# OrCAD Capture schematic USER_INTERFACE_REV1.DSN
size A; title: User Interface Schematic; rev: <Rev1>
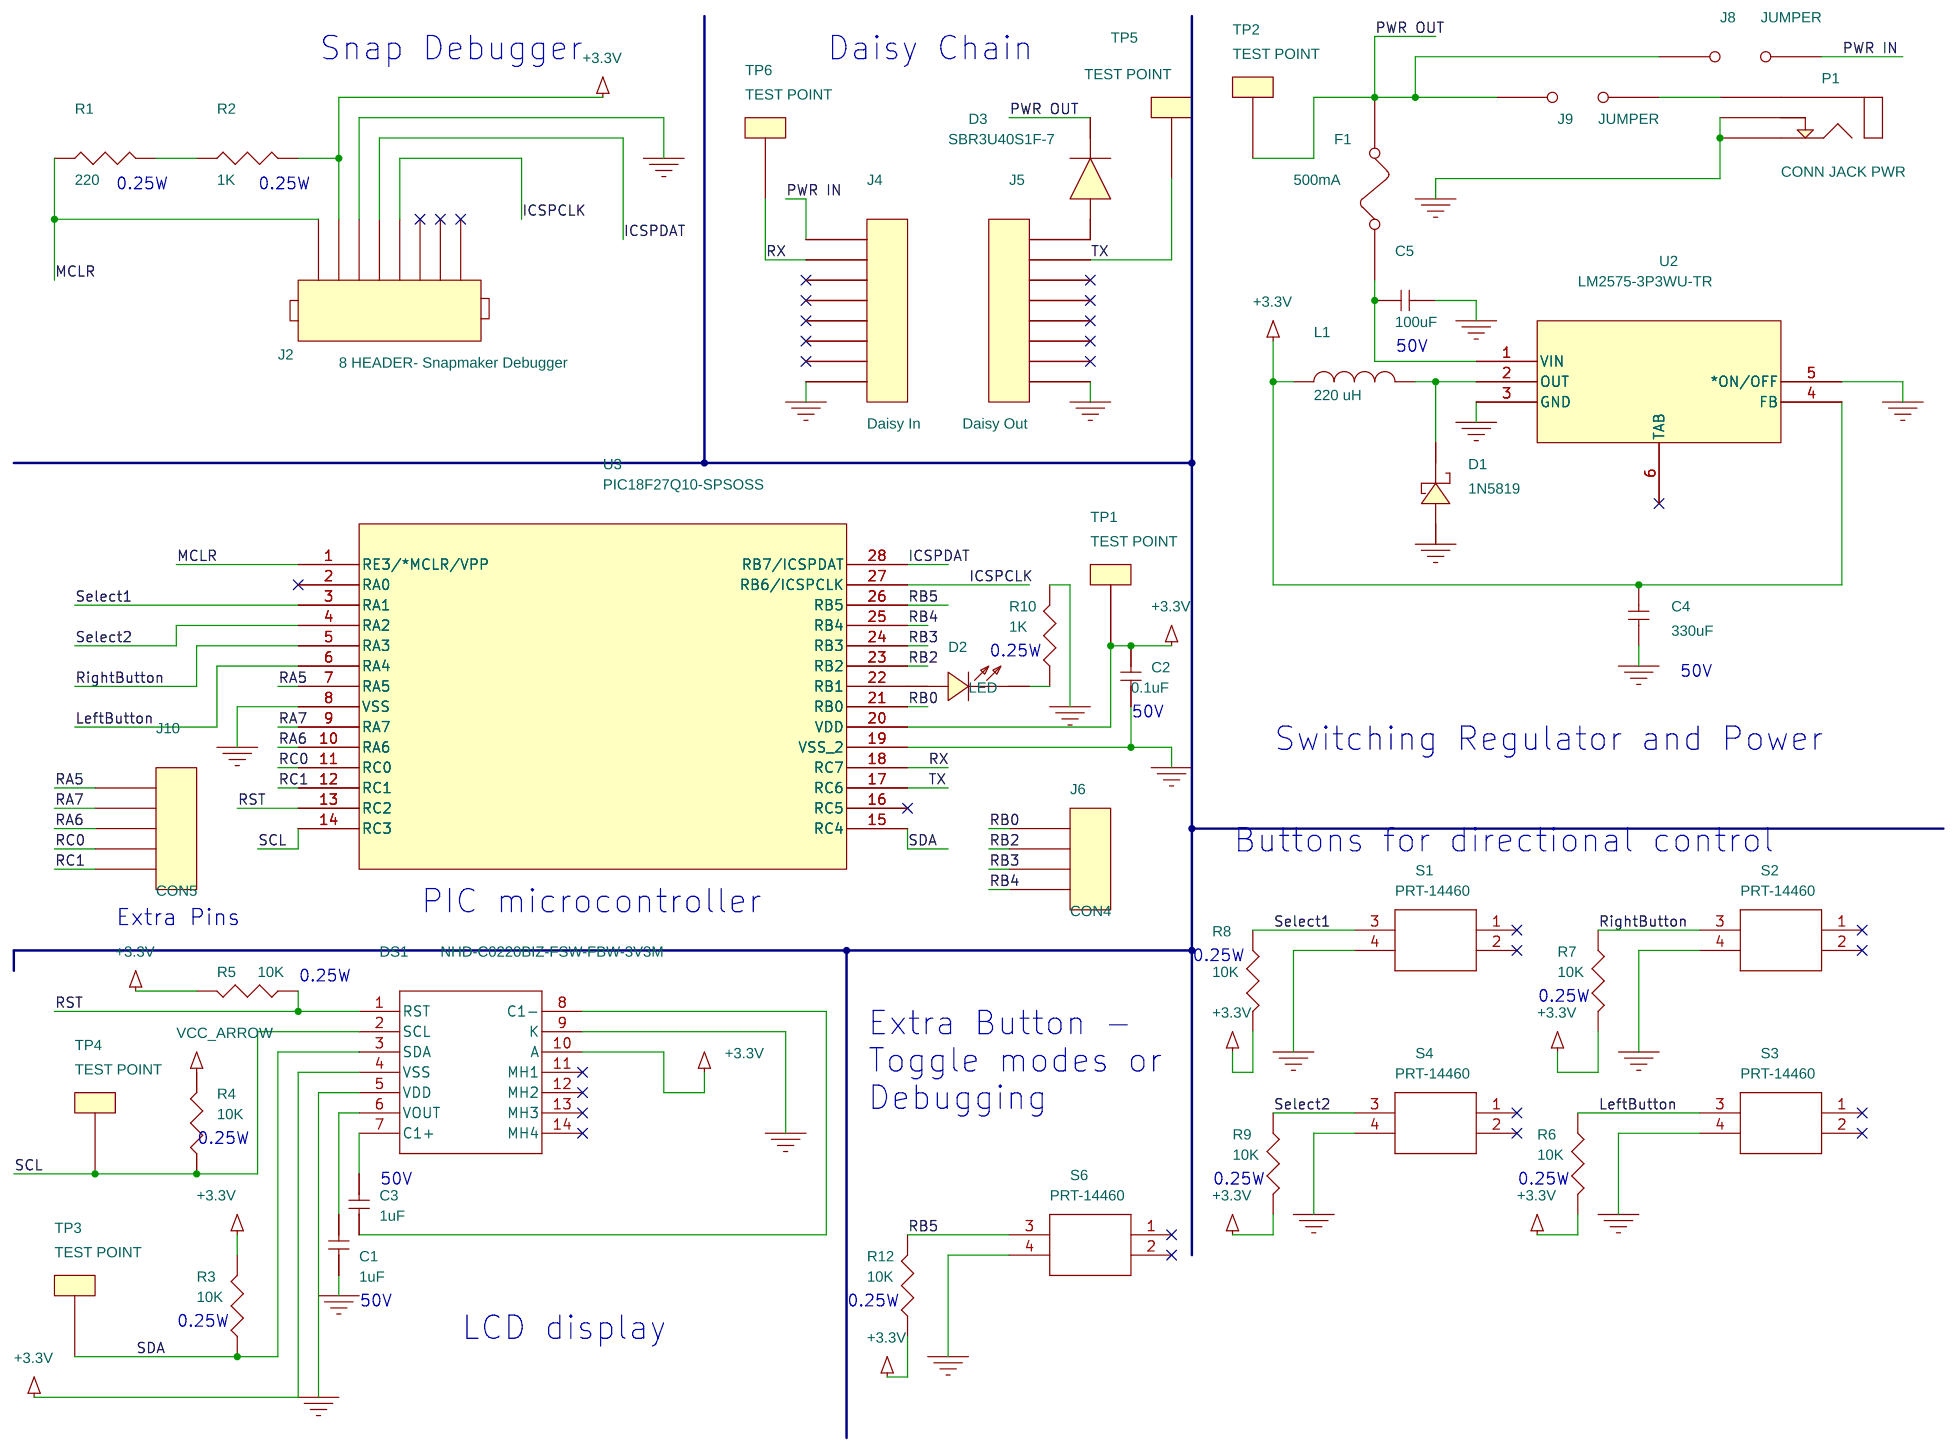
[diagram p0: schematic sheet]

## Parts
C1  1uF  [CAP_WCAP-ASLI_04p0X05p5_WRE]
C2  0.1uF  [CAPC2012X147N]
C3  1uF  [CAP_WCAP-ASLI_04p0X05p5_WRE]
C4  330uF  [CAPAE830X1050N]
C5  100uF  [CAPAE660X770N]
D1  1N5819  [SOD3716X145N]
D2  LED  [T1341NB30C000112U1930]
D3  SBR3U40S1F-7  [SODFL3518X115N]
DS1  NHD-C0220BIZ-FSW-FBW-3V3M  [NHDC0220BIZFSWFBW3V3M]
F1  500mA  [FUSE_354101-GY_LTF]
J2  8 HEADER- Snapmaker Debugger  [jumper8]
J4  Daisy In  [jumper8]
J5  Daisy Out  [jumper8]
J6  CON4  [jumper4]
J8  JUMPER  [jumper2]
J9  JUMPER  [jumper2]
J10  CON5  [jumper5]
L1  220 uH  [IND_BOURNS_SRN1060]
P1  CONN JACK PWR  [694108301002]
R1  220  [RESC3216X75N]
R2  1K  [RESC3216X75N]
R3  10K  [RESC3216X75N]
R4  10K  [RESC3216X75N]
R5  10K  [RESC3216X75N]
R6  10K  [RESC3216X75N]
R7  10K  [RESC3216X75N]
R8  10K  [RESC3216X75N]
R9  10K  [RESC3216X75N]
R10  1K  [RESC3216X75N]
R12  10K  [RESC3216X75N]
S1  PRT-14460  [PRT14460]
S2  PRT-14460  [PRT14460]
S3  PRT-14460  [PRT14460]
S4  PRT-14460  [PRT14460]
S6  PRT-14460  [PRT14460]
TP1  TEST POINT  [CONN1_5011_KEY]
TP2  TEST POINT  [CONN1_5011_KEY]
TP3  TEST POINT  [CONN1_5011_KEY]
TP4  TEST POINT  [CONN1_5011_KEY]
TP5  TEST POINT  [CONN1_5011_KEY]
TP6  TEST POINT  [CONN1_5011_KEY]
U2  LM2575-3P3WU-TR  [MIC29302WU]
U3  PIC18F27Q10-SPSOSS  [SOIC28_SO_MCH]

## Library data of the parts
C1-C5 = C: AppProp: InductiveSlave:;SRF:;PrevCap:1u;PrevESL:
D1 = DIODE_SCHOTTKY
D2 = LED
D3 = SBR3U40S1F-7: Manufacturer Name: Diodes Incorporated; Source Id: SamacSys
DS1 = NHD-C0220BIZ-FSW-FBW-3V3M: Manufacturer Name: Newhaven Display; Source Id: SamacSys
F1 = FUSE
J2 = 8_HEADER
J4 J5 = CON8
J6 = CON4
J8 J9 = JUMPER
J10 = CON5
L1 = INDUCTOR
P1 = CONN_JACK_PWR
R1-R10 R12 = RESISTOR
S1-S4 S6 = PRT-14460: Manufacturer Name: SparkFun; Source Id: SamacSys
TP1-TP6 = TEST_POINT
U2 = LM2575-3P3WU-TR_2
U3 = PIC18F27Q10T-ISO: Distributor Id: Digi-Key; Distributor Part Number: PIC18F27Q10T-I/SOTR-ND; Manufacturer Name: Microchip; Manufacturer Part Number: PIC18F27Q10T-I/SO; Part Number: PIC18F27Q10T-I/SO; Source Id: UL

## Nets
+3.3V: C2.2 C4.2 DS1.4(VSS) DS1.10(A) J2.2 L1.1 R2.2 R3.2 R4.2 R5.2 R6.2 R7.2 R8.2 R9.2 R12.1 TP1.1 U2.4(FB) U3.20(VDD)
GND: C1.1 C2.1 C4.1 C5.1 D1.1(ANODE) DS1.5(VDD) DS1.9(K) J2.3 J4.8 J5.8 P1.2 P1.3 R10.2 S1.4 S2.4 S3.4 S4.4 S6.4 U2.3(GND) U2.5(*ON/OFF) U3.8(VSS) U3.19(VSS_2)
ICSPCLK: J2.5 U3.27(RB6/ICSPCLK)
ICSPDAT: J2.4 U3.28(RB7/ICSPDAT)
LeftButton: R6.1 S3.3 U3.6(RA4)
MCLR: J2.1 R1.1 U3.1(RE3/*MCLR/VPP)
PWR IN: J4.1 J8.2
PWR OUT: D3.1(K) F1.2 J8.1 J9.1 TP2.1
RA5: J10.1 U3.7(RA5)
RA6: J10.3 U3.10(RA6)
RA7: J10.2 U3.9(RA7)
RB0: J6.1 U3.21(RB0)
RB2: J6.2 U3.23(RB2)
RB3: J6.3 U3.24(RB3)
RB4: J6.4 U3.25(RB4)
RB5: R12.2 S6.3 U3.26(RB5)
RC0: J10.4 U3.11(RC0)
RC1: J10.5 U3.12(RC1)
RightButton: R7.1 S2.3 U3.5(RA3)
RST: DS1.1(RST) R5.1 U3.13(RC2)
RX: J4.2 TP6.1 U3.18(RC7)
SCL: DS1.2(SCL) R4.1 TP4.1 U3.14(RC3)
SDA: DS1.3(SDA) R3.1 TP3.1 U3.15(RC4)
Select1: R8.1 S1.3 U3.3(RA1)
Select2: R9.1 S4.3 U3.4(RA2)
TX: J5.2 TP5.1 U3.17(RC6)
N01597: R1.2 R2.1
N05849: D1.2(CATHODE) L1.2 U2.2(OUT)
N06927: C5.2 F1.1 U2.1(VIN)
N30188: D2.1(CATHODE) R10.1
N40798: C1.2 DS1.6(VOUT)
N40848: C3.1 DS1.7(C1+)
N40866: C3.2 DS1.8(C1-)
N41411: J9.2 P1.1
N45892: D3.2(A) J5.1
N47132: D2.2(ANODE) U3.22(RB1)

Not connected (* = marked no-connect by the designer): DS1 11(MH1)* 12(MH2)* 13(MH3)* 14(MH4)*; J2 6* 7* 8*; J4 3* 4* 5* 6* 7*; J5 3* 4* 5* 6* 7*; S1 1* 2*; S2 1* 2*; S3 1* 2*; S4 1* 2*; S6 1* 2*; U2 6(TAB)*; U3 2(RA0)* 16(RC5)*

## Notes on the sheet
- Snap Debugger
- Daisy Chain
- 0.25W
- 0.25W
- 50V
- 0.25W
- 50V
- 50V
- Switching Regulator and Power
- Buttons for directional control
- PIC microcontroller
- Extra Pins
- 0.25W
- 0.25W
- Extra Button -
  Toggle modes or
  Debugging
- 0.25W
- 0.25W
- 50V
- 0.25W
- 0.25W
- 50V
- 0.25W
- 0.25W
- LCD display
